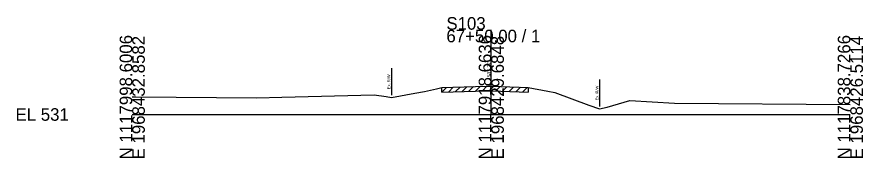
# Model space of a CAD drawing. Extents: x -26 to 163, y -10 to 24018.
# Drawn here: x -25.7 to 162.8, y 15490.3 to 15521.7 of the extents above; entities that cross this region are included whole.
import ezdxf

# ---------------------------------------------------------------- set-up
doc = ezdxf.new("R2010")
doc.units = 0
for name, color, linetype in [('RD_GPK_XS_Cell', 7, 'Continuous'), ('RD_XS_ExGround', 7, 'Continuous'), ('RD_XS_ExPaveRet', 7, 'Continuous'), ('RD_XS_ExRW', 7, 'Continuous'), ('RD_XS_TX_Elev_EX', 7, 'Continuous')]:
    doc.layers.add(name, color=color, linetype=linetype)

msp = doc.modelspace()

# ---------------------------------------------------------------- linework, layer by layer
at = {"layer": 'RD_GPK_XS_Cell'}
for p, q in [((80, 15500), (80, 15518.86)), ((0, 15500), (80, 15500)), ((80, 15500), (160, 15500))]:
    msp.add_line(p, q, dxfattribs=at)
at = {"layer": 'RD_XS_ExGround'}
msp.add_lwpolyline([(0, 15503.89), (0.81, 15503.9), (27.77, 15503.72), (33.3, 15503.85), (53.92, 15504.35), (56.59, 15503.99), (57.74, 15503.78), (63, 15504.72), (65.13, 15505.12), (67.77, 15505.74), (69.01, 15506), (76.47, 15506.21), (79.48, 15506.29), (80, 15506.27), (82.15, 15506.2), (88.24, 15506), (92.58, 15505.16), (94.14, 15504.87), (101.7, 15502.09), (104.13, 15501.28), (105.81, 15501.64), (110.87, 15503.09), (120.83, 15502.55), (160, 15502.22)], dxfattribs=at)
at = {"layer": 'RD_XS_ExPaveRet'}
for p, q in [((69.01, 15505), (70.04, 15506.03)), ((69.01, 15505), (69.01, 15506)), ((69.01, 15505), (76.47, 15505.21)), ((70.51, 15505.04), (71.54, 15506.07)), ((72.01, 15505.08), (73.04, 15506.11)), ((73.51, 15505.12), (74.54, 15506.15)), ((75.01, 15505.17), (76.04, 15506.2)), ((76.47, 15505.21), (79.48, 15505.29)), ((76.51, 15505.21), (77.54, 15506.24)), ((78.01, 15505.25), (79.04, 15506.27)), ((79.48, 15505.29), (80, 15505.27)), ((79.51, 15505.28), (80.48, 15506.25)), ((80, 15505.27), (82.15, 15505.2)), ((81.01, 15505.24), (81.98, 15506.2)), ((82.15, 15505.2), (88.24, 15505)), ((82.51, 15505.19), (83.48, 15506.16)), ((84.01, 15505.14), (84.98, 15506.11)), ((85.51, 15505.09), (86.48, 15506.06)), ((87.01, 15505.04), (87.98, 15506.01)), ((88.24, 15506), (88.24, 15505))]:
    msp.add_line(p, q, dxfattribs=at)
at = {"layer": 'RD_XS_ExRW'}
for p, q in [((57.74, 15510.28), (57.74, 15504.28)), ((104.13, 15507.78), (104.13, 15501.78))]:
    msp.add_line(p, q, dxfattribs=at)

# ---------------------------------------------------------------- texts
at = {"layer": 'RD_GPK_XS_Cell'}
for s, p in [('S103', (70, 15518.86)), ('67+50.00 / 1', (70, 15516.06)), ('EL 531', (-26, 15498.6))]:
    msp.add_text(s, height=2.8, dxfattribs=at).set_placement(p)
for s, p in [('N 1117998.6006', (0, 15490)), ('E 1968432.8582', (2.8, 15490)), ('N 1117918.6636', (80, 15490)), ('E 1968429.6848', (82.8, 15490)), ('N 1117838.7266', (160, 15490)), ('E 1968426.5114', (162.8, 15490))]:
    msp.add_text(s, height=2.8, rotation=90, dxfattribs=at).set_placement(p)
at = {"layer": 'RD_XS_ExRW'}
for p in [(57.49, 15505.63), (103.88, 15503.12)]:
    msp.add_text('Ex. R/W ', height=0.65, rotation=90, dxfattribs=at).set_placement(p)
at = {"layer": 'RD_XS_TX_Elev_EX'}
msp.add_text('537.27', height=0.8, rotation=90, dxfattribs=at).set_placement((79.9, 15508.27))

doc.saveas('drawing.dxf')
